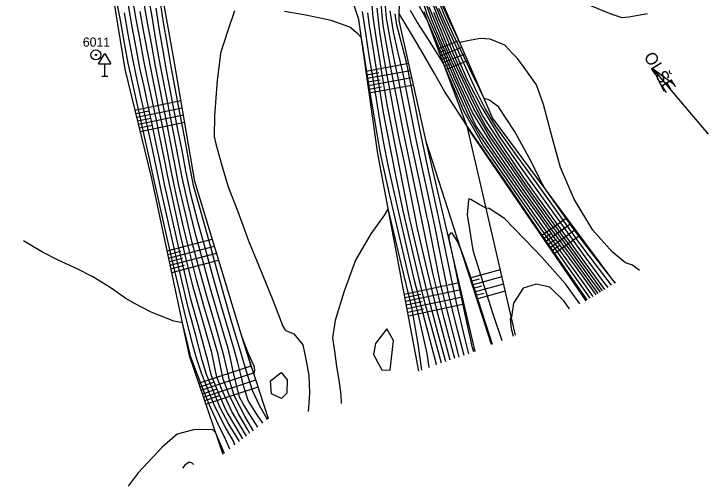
# Model space of a CAD drawing. Extents: x -448957 to -448612, y -1107690 to -1107245.
# Drawn here: x -448752.7 to -448695.5, y -1107690 to -1107651.1 of the extents above; entities that cross this region are included whole.
import ezdxf

# ---------------------------------------------------------------- set-up
doc = ezdxf.new("R2010")
doc.units = 0
for name, color, linetype in [('34', 7, 'Continuous'), ('63', 7, 'Continuous'), ('Default', 7, 'Continuous'), ('Vrstva 1', 7, 'Continuous'), ('Vrstva 14', 7, 'Continuous'), ('Vrstva 15', 7, 'Continuous'), ('Vrstva 16', 7, 'Continuous'), ('Vrstva 17', 7, 'Continuous'), ('Vrstva 2', 7, 'Continuous'), ('Vrstva 34', 7, 'Continuous'), ('Vrstva 45', 7, 'Continuous'), ('Vrstva 63', 7, 'Continuous')]:
    doc.layers.add(name, color=color, linetype=linetype)

# ---------------------------------------------------------------- blocks, each defined once
blk = doc.blocks.new('POINT_DISPLAY')
at = {"layer": 'Default'}
blk.add_line((0, 0), (0, 0), dxfattribs=at)
blk = doc.blocks.new('DZ$0')
at = {"layer": '34'}
for p, q in [((-5, 10), (0, 18.5)), ((0, 18.5), (5, 10)), ((-5, 10), (5, 10)), ((0, 0), (0, 10)), ((-2.49, 0), (2.49, 0))]:
    blk.add_line(p, q, dxfattribs=at)
blk = doc.blocks.new('PPBP$7')
at = {"layer": '63'}
for radius in [4.12, 0.5]:
    blk.add_circle((0, 0), radius, dxfattribs=at)
blk = doc.blocks.new('TOK')
at = {"layer": 'Default'}
for p, q in [((-5, 50), (0, 70)), ((0, 0), (0, 70)), ((0, 70), (5, 50))]:
    blk.add_line(p, q, dxfattribs=at)

msp = doc.modelspace()

# ---------------------------------------------------------------- linework, layer by layer
at = {"layer": 'Vrstva 14'}
for p, q in [((-448724.467, -1107651.591), (-448727.762, -1107641.454)), ((-448721.159, -1107651.66), (-448721.006, -1107642.964)), ((-448743.592, -1107655.643), (-448745.343, -1107644.83)), ((-448739.604, -1107654.794), (-448741.442, -1107644.579)), ((-448713.524, -1107659.615), (-448717.674, -1107650.095)), ((-448715.567, -1107660.428), (-448719.111, -1107650.966)), ((-448722.898, -1107662.583), (-448724.467, -1107651.591)), ((-448718.945, -1107661.555), (-448721.159, -1107651.66)), ((-448737.889, -1107664.827), (-448739.604, -1107654.794)), ((-448741.412, -1107664.597), (-448743.592, -1107655.643)), ((-448703.496, -1107673.142), (-448713.524, -1107659.615)), ((-448705.856, -1107674.58), (-448715.567, -1107660.428)), ((-448711.633, -1107677.388), (-448715.567, -1107660.428)), ((-448714.928, -1107678.724), (-448718.945, -1107661.555)), ((-448713.608, -1107678.158), (-448718.945, -1107661.555)), ((-448719.553, -1107680.342), (-448722.898, -1107662.583)), ((-448738.314, -1107679.081), (-448741.412, -1107664.597)), ((-448733.908, -1107677.93), (-448737.889, -1107664.827)), ((-448731.852, -1107684.228), (-448733.908, -1107677.93)), ((-448735.572, -1107687.149), (-448738.314, -1107679.081))]:
    msp.add_line(p, q, dxfattribs=at)
at = {"layer": 'Vrstva 15'}
for p, q in [((-448717.978, -1107653.99), (-448716.276, -1107653.301)), ((-448717.873, -1107654.271), (-448717.378, -1107654.071)), ((-448717.768, -1107654.552), (-448716.037, -1107653.851)), ((-448717.663, -1107654.833), (-448717.159, -1107654.63)), ((-448717.557, -1107655.114), (-448715.797, -1107654.401)), ((-448723.866, -1107655.804), (-448720.375, -1107655.165)), ((-448717.452, -1107655.395), (-448716.941, -1107655.188)), ((-448717.347, -1107655.676), (-448715.557, -1107654.952)), ((-448723.823, -1107656.101), (-448722.813, -1107655.916)), ((-448723.781, -1107656.398), (-448720.244, -1107655.751)), ((-448723.738, -1107656.696), (-448722.715, -1107656.508)), ((-448723.696, -1107656.993), (-448720.112, -1107656.337)), ((-448723.654, -1107657.29), (-448722.616, -1107657.1)), ((-448723.611, -1107657.587), (-448719.981, -1107656.923)), ((-448742.777, -1107658.989), (-448739.02, -1107658.211)), ((-448742.635, -1107659.572), (-448738.919, -1107658.803)), ((-448742.706, -1107659.281), (-448741.644, -1107659.061)), ((-448742.493, -1107660.155), (-448738.818, -1107659.395)), ((-448742.564, -1107659.864), (-448741.514, -1107659.646)), ((-448742.351, -1107660.739), (-448738.716, -1107659.987)), ((-448742.422, -1107660.447), (-448741.384, -1107660.232)), ((-448709.512, -1107669.252), (-448707.463, -1107667.791)), ((-448709.172, -1107669.747), (-448707.106, -1107668.273)), ((-448709.342, -1107669.5), (-448708.752, -1107669.078)), ((-448708.833, -1107670.242), (-448706.748, -1107668.755)), ((-448740.149, -1107670.5), (-448736.455, -1107669.545)), ((-448709.003, -1107669.994), (-448708.407, -1107669.57)), ((-448708.493, -1107670.737), (-448706.391, -1107669.237)), ((-448740.024, -1107671.087), (-448736.281, -1107670.12)), ((-448708.663, -1107670.489), (-448708.062, -1107670.061)), ((-448740.087, -1107670.793), (-448739.017, -1107670.517)), ((-448739.898, -1107671.674), (-448736.106, -1107670.694)), ((-448739.961, -1107671.38), (-448738.878, -1107671.101)), ((-448739.773, -1107672.261), (-448735.932, -1107671.269)), ((-448739.835, -1107671.968), (-448738.738, -1107671.684)), ((-448715.361, -1107672.706), (-448712.878, -1107672.02)), ((-448720.741, -1107674.034), (-448716.247, -1107673.085)), ((-448715.269, -1107672.992), (-448714.573, -1107672.8)), ((-448715.177, -1107673.278), (-448712.742, -1107672.605)), ((-448720.63, -1107674.624), (-448716.111, -1107673.67)), ((-448715.085, -1107673.563), (-448714.403, -1107673.375)), ((-448714.993, -1107673.849), (-448712.607, -1107673.19)), ((-448720.686, -1107674.329), (-448719.394, -1107674.056)), ((-448720.519, -1107675.213), (-448715.974, -1107674.254)), ((-448714.901, -1107674.135), (-448714.233, -1107673.951)), ((-448714.809, -1107674.421), (-448712.471, -1107673.775)), ((-448720.575, -1107674.918), (-448719.276, -1107674.644)), ((-448720.408, -1107675.803), (-448715.837, -1107674.838)), ((-448720.463, -1107675.508), (-448719.158, -1107675.233)), ((-448737.551, -1107681.326), (-448733.265, -1107679.899)), ((-448737.358, -1107681.894), (-448733.079, -1107680.469)), ((-448737.165, -1107682.463), (-448732.893, -1107681.039)), ((-448737.454, -1107681.61), (-448736.232, -1107681.203)), ((-448736.972, -1107683.031), (-448732.707, -1107681.61)), ((-448737.261, -1107682.179), (-448736.041, -1107681.772)), ((-448737.068, -1107682.747), (-448735.85, -1107682.341))]:
    msp.add_line(p, q, dxfattribs=at)
at = {"layer": 'Vrstva 16'}
for points in [[(-448705.049, -1107674.088), (-448705.094, -1107674.027), (-448706.742, -1107671.759), (-448708.493, -1107669.348), (-448709.575, -1107667.84), (-448711.005, -1107665.85), (-448711.595, -1107665.027), (-448713.199, -1107662.695), (-448714.823, -1107660.339), (-448714.994, -1107660.039), (-448715.689, -1107658.504), (-448716.634, -1107656.378), (-448718.17, -1107652.827), (-448718.828, -1107651.263), (-448719.336, -1107649.7)], [(-448734.596, -1107686.383), (-448734.729, -1107686.068), (-448735.394, -1107684.887), (-448736.238, -1107683.234), (-448736.762, -1107681.942), (-448737.326, -1107680.512), (-448737.745, -1107679.269), (-448738.038, -1107678.173), (-448738.64, -1107675.835), (-448739.163, -1107673.647), (-448739.728, -1107671.23), (-448740.249, -1107668.973), (-448740.791, -1107666.557), (-448741.278, -1107664.37), (-448741.624, -1107662.849), (-448741.978, -1107661.301), (-448742.3, -1107659.8), (-448742.646, -1107658.212), (-448742.99, -1107656.716), (-448743.335, -1107655.149), (-448743.656, -1107653.373), (-448743.963, -1107651.649), (-448744.304, -1107649.85)], [(-448704.067, -1107673.49), (-448704.487, -1107672.947), (-448706.153, -1107670.689), (-448707.934, -1107668.22), (-448709.565, -1107665.94), (-448711.34, -1107663.483), (-448712.956, -1107661.156), (-448714.517, -1107658.573), (-448715.298, -1107657.072), (-448715.555, -1107656.538), (-448716.244, -1107654.957), (-448716.907, -1107653.416), (-448717.597, -1107651.828), (-448718.296, -1107650.163)], [(-448733.099, -1107685.207), (-448733.105, -1107685.197), (-448733.776, -1107684.021), (-448734.661, -1107682.335), (-448735.028, -1107681.178), (-448735.237, -1107680.235), (-448735.479, -1107679.159), (-448736.195, -1107676.593), (-448736.843, -1107674.405), (-448737.502, -1107672.045), (-448738.105, -1107669.824), (-448738.627, -1107667.568), (-448739.179, -1107665.151), (-448739.518, -1107663.426), (-448739.839, -1107661.752), (-448740.145, -1107660.186), (-448740.465, -1107658.559), (-448740.798, -1107656.902), (-448741.102, -1107655.397), (-448741.412, -1107653.697), (-448741.714, -1107651.994), (-448742.018, -1107650.283)], [(-448717.703, -1107679.695), (-448718.244, -1107677.695), (-448719.024, -1107674.813), (-448719.335, -1107673.622), (-448720.832, -1107667.226), (-448721.44, -1107664.331), (-448722.12, -1107660.874), (-448722.438, -1107659.189), (-448722.72, -1107657.481), (-448723.022, -1107655.648), (-448723.298, -1107653.91), (-448723.59, -1107652.078), (-448723.727, -1107651.045)], [(-448715.847, -1107679.045), (-448716.429, -1107676.776), (-448717.144, -1107673.885), (-448717.657, -1107671.34), (-448718.246, -1107668.457), (-448718.821, -1107665.787), (-448719.444, -1107662.914), (-448719.848, -1107660.983), (-448720.175, -1107659.323), (-448720.526, -1107657.559), (-448720.854, -1107655.899), (-448721.235, -1107654.326), (-448721.627, -1107652.594), (-448721.889, -1107650.873)], [(-448707.229, -1107675.247), (-448707.687, -1107674.599), (-448708.837, -1107673.46), (-448709.961, -1107673.235), (-448711.019, -1107673.565), (-448711.811, -1107674.768), (-448711.976, -1107675.909), (-448712.076, -1107676.062), (-448712.006, -1107676.841), (-448711.836, -1107677.467)]]:
    msp.add_lwpolyline(points, dxfattribs=at)
at = {"layer": 'Vrstva 17'}
for points in [[(-448703.454, -1107673.12), (-448703.493, -1107673.078), (-448703.664, -1107672.887), (-448703.796, -1107672.737), (-448705.19, -1107670.934), (-448706.748, -1107668.904), (-448708.093, -1107667.014), (-448709.273, -1107665.349), (-448709.634, -1107664.685), (-448710.393, -1107663.155), (-448711.735, -1107660.719), (-448713.043, -1107658.718), (-448713.81, -1107658.161), (-448714.213, -1107658.034), (-448714.594, -1107657.258), (-448715.069, -1107656.264), (-448715.82, -1107654.713), (-448716.755, -1107652.751), (-448717.475, -1107651.182), (-448718.322, -1107649.043)], [(-448732.713, -1107684.904), (-448733.21, -1107684.149), (-448733.927, -1107683.008), (-448734.217, -1107682.455), (-448734.504, -1107681.354), (-448734.762, -1107680.238), (-448734.975, -1107679.291), (-448735.189, -1107678.382), (-448735.292, -1107678.037), (-448735.942, -1107675.849), (-448736.603, -1107673.601), (-448737.208, -1107671.402), (-448737.866, -1107669.027), (-448738.437, -1107666.658), (-448738.921, -1107664.501), (-448739.238, -1107662.827), (-448739.541, -1107661.244), (-448739.865, -1107659.57), (-448740.169, -1107657.995), (-448740.466, -1107656.482), (-448740.791, -1107654.794), (-448741.086, -1107653.089), (-448741.385, -1107651.345), (-448741.678, -1107649.64)], [(-448704.329, -1107673.649), (-448705.956, -1107671.422), (-448707.61, -1107669.158), (-448708.038, -1107668.568), (-448709.676, -1107666.293), (-448711.034, -1107664.404), (-448712.63, -1107662.042), (-448714.306, -1107659.462), (-448715.07, -1107657.954), (-448715.991, -1107656.035), (-448716.683, -1107654.473), (-448717.291, -1107653.016), (-448717.965, -1107651.418), (-448718.644, -1107649.622)], [(-448701.507, -1107672.098), (-448702.053, -1107671.676), (-448702.651, -1107671.474), (-448703.702, -1107670.605), (-448705.315, -1107668.823), (-448706.853, -1107666.268), (-448707.957, -1107663.7), (-448708.623, -1107661.323), (-448709.345, -1107658.545), (-448709.931, -1107656.94), (-448710.806, -1107655.701), (-448711.467, -1107654.782), (-448711.845, -1107654.386), (-448712.526, -1107653.694), (-448713.704, -1107653.191), (-448714.53, -1107653.144), (-448715.41, -1107653.296), (-448716.203, -1107653.47), (-448716.251, -1107653.372), (-448716.313, -1107653.244), (-448717.048, -1107651.684), (-448717.931, -1107649.679)], [(-448733.661, -1107685.648), (-448734.17, -1107684.793), (-448734.856, -1107683.628), (-448735.549, -1107682.095), (-448736.077, -1107680.825), (-448736.264, -1107679.899), (-448736.487, -1107678.818), (-448736.675, -1107678.146), (-448737.315, -1107675.956), (-448737.975, -1107673.657), (-448738.554, -1107671.298), (-448739.076, -1107669.07), (-448739.612, -1107666.655), (-448740.095, -1107664.427), (-448740.43, -1107662.751), (-448740.74, -1107661.209), (-448741.053, -1107659.693), (-448741.39, -1107658.059), (-448741.715, -1107656.559), (-448742.053, -1107654.951), (-448742.367, -1107653.25), (-448742.678, -1107651.57), (-448742.99, -1107649.788)], [(-448731.936, -1107684.294), (-448732.027, -1107684.155), (-448732.6, -1107683.143), (-448733.15, -1107681.928), (-448733.477, -1107680.874), (-448733.807, -1107679.834), (-448734.115, -1107678.775), (-448734.812, -1107676.455), (-448735.452, -1107674.265), (-448736.111, -1107671.907), (-448736.712, -1107669.707), (-448737.371, -1107667.373), (-448737.985, -1107665.148), (-448738.314, -1107663.434), (-448738.622, -1107661.761), (-448738.927, -1107660.193), (-448739.253, -1107658.518), (-448739.551, -1107656.912), (-448739.855, -1107655.285), (-448740.156, -1107653.532), (-448740.44, -1107651.825), (-448740.723, -1107650.003)], [(-448716.618, -1107679.315), (-448716.724, -1107678.925), (-448717.469, -1107676.031), (-448718.393, -1107672.329), (-448719.015, -1107669.432), (-448719.514, -1107666.916), (-448720.117, -1107664.038), (-448720.834, -1107660.626), (-448721.169, -1107658.968), (-448721.521, -1107657.212), (-448721.851, -1107655.532), (-448722.143, -1107653.892), (-448722.464, -1107652.059), (-448722.557, -1107651.204), (-448722.635, -1107650.216)], [(-448704.869, -1107673.979), (-448705.309, -1107673.376), (-448706.959, -1107671.109), (-448708.712, -1107668.694), (-448710.377, -1107666.379), (-448711.88, -1107664.245), (-448713.496, -1107661.885), (-448715.152, -1107659.205), (-448715.867, -1107657.677), (-448716.266, -1107656.784), (-448716.942, -1107655.241), (-448717.83, -1107653.204), (-448718.485, -1107651.623), (-448719.038, -1107650.065)], [(-448733.941, -1107685.869), (-448734.518, -1107684.901), (-448735.211, -1107683.743), (-448735.367, -1107683.455), (-448735.903, -1107682.173), (-448736.505, -1107680.712), (-448736.789, -1107679.584), (-448737.573, -1107676.647), (-448738.208, -1107674.445), (-448738.73, -1107672.222), (-448739.297, -1107669.805), (-448739.815, -1107667.469), (-448740.349, -1107665.054), (-448740.695, -1107663.383), (-448741.035, -1107661.75), (-448741.377, -1107660.142), (-448741.691, -1107658.639), (-448742.038, -1107657.059), (-448742.37, -1107655.56), (-448742.688, -1107653.905), (-448743.006, -1107652.193), (-448743.31, -1107650.453)], [(-448732.324, -1107684.599), (-448732.84, -1107683.814), (-448733.522, -1107682.729), (-448733.834, -1107681.705), (-448734.104, -1107680.636), (-448734.373, -1107679.645), (-448734.652, -1107678.579), (-448735.052, -1107677.246), (-448735.697, -1107675.057), (-448736.357, -1107672.754), (-448736.96, -1107670.554), (-448737.618, -1107668.2), (-448738.211, -1107665.903), (-448738.618, -1107663.968), (-448738.93, -1107662.294), (-448739.234, -1107660.719), (-448739.559, -1107659.044), (-448739.86, -1107657.454), (-448740.16, -1107655.883), (-448740.473, -1107654.163), (-448740.763, -1107652.457), (-448741.054, -1107650.674)], [(-448717.342, -1107679.568), (-448717.961, -1107677.279), (-448718.732, -1107674.394), (-448719.514, -1107671.143), (-448720.203, -1107668.229), (-448720.275, -1107667.921), (-448720.356, -1107667.524), (-448720.851, -1107665.017), (-448721.346, -1107662.528), (-448721.461, -1107661.982), (-448721.785, -1107660.321), (-448722.133, -1107658.539), (-448722.44, -1107656.742), (-448722.723, -1107655.043), (-448723.015, -1107653.21), (-448723.277, -1107651.411), (-448723.369, -1107650.422)], [(-448716.98, -1107679.442), (-448717.342, -1107678.102), (-448718.101, -1107675.213), (-448718.99, -1107671.58), (-448719.647, -1107668.675), (-448720.143, -1107666.165), (-448720.732, -1107663.283), (-448721.148, -1107661.304), (-448721.477, -1107659.645), (-448721.827, -1107657.876), (-448722.146, -1107656.137), (-448722.433, -1107654.468), (-448722.739, -1107652.635), (-448722.957, -1107650.665)], [(-448716.239, -1107679.183), (-448716.702, -1107677.374), (-448717.444, -1107674.478), (-448717.796, -1107673.079), (-448718.297, -1107670.622), (-448718.797, -1107668.102), (-448718.884, -1107667.67), (-448719.453, -1107665.012), (-448720.07, -1107662.137), (-448720.165, -1107661.682), (-448720.499, -1107660.024), (-448720.852, -1107658.274), (-448721.183, -1107656.615), (-448721.546, -1107654.929), (-448721.897, -1107653.134), (-448722.183, -1107651.476), (-448722.278, -1107650.487)], [(-448705.525, -1107674.378), (-448706.275, -1107673.339), (-448707.908, -1107671.022), (-448709.414, -1107668.884), (-448711.056, -1107666.535), (-448712.671, -1107664.183), (-448714.308, -1107661.832), (-448715.878, -1107659.074), (-448716.534, -1107657.523), (-448717.095, -1107656.216), (-448717.528, -1107655.193), (-448717.839, -1107654.694), (-448718.773, -1107653.227), (-448719.701, -1107651.764), (-448720.232, -1107650.845)], [(-448705.284, -1107674.231), (-448706.58, -1107672.434), (-448708.218, -1107670.143), (-448709.663, -1107668.122), (-448711.325, -1107665.781), (-448712.935, -1107663.439), (-448714.566, -1107661.085), (-448715.436, -1107659.557), (-448716.111, -1107658.013), (-448717.002, -1107655.971), (-448717.663, -1107654.422), (-448718.351, -1107652.823), (-448718.885, -1107651.57), (-448719.064, -1107651.291), (-448719.509, -1107650.522)], [(-448704.689, -1107673.869), (-448705.525, -1107672.725), (-448707.176, -1107670.458), (-448708.931, -1107668.04), (-448710.589, -1107665.741), (-448712.17, -1107663.456), (-448713.777, -1107661.093), (-448715.078, -1107658.842), (-448715.81, -1107657.322), (-448716.259, -1107656.365), (-448716.945, -1107654.826), (-448717.49, -1107653.581), (-448718.142, -1107651.982), (-448718.696, -1107650.579)], [(-448703.777, -1107673.313), (-448704.761, -1107672.04), (-448706.451, -1107669.796), (-448708.266, -1107667.26), (-448709.891, -1107664.978), (-448711.645, -1107662.562), (-448713.282, -1107660.27), (-448714.111, -1107658.858), (-448714.886, -1107657.338), (-448715.685, -1107655.585), (-448716.398, -1107654.011), (-448717.196, -1107652.259), (-448717.902, -1107650.681)], [(-448700.829, -1107651.137), (-448702.369, -1107651.4), (-448702.907, -1107651.463), (-448703.82, -1107651.145), (-448705.475, -1107650.46)], [(-448734.222, -1107686.089), (-448734.384, -1107685.818), (-448735.087, -1107684.666), (-448735.803, -1107683.345), (-448736.333, -1107682.057), (-448736.916, -1107680.612), (-448737.267, -1107679.426), (-448737.806, -1107677.41), (-448738.424, -1107675.14), (-448738.946, -1107672.935), (-448739.512, -1107670.518), (-448740.032, -1107668.221), (-448740.57, -1107665.806), (-448740.987, -1107663.876), (-448741.33, -1107662.299), (-448741.677, -1107660.722), (-448741.996, -1107659.22), (-448742.342, -1107657.636), (-448742.68, -1107656.138), (-448743.011, -1107654.527), (-448743.331, -1107652.783), (-448743.637, -1107651.051)], [(-448733.38, -1107685.428), (-448733.637, -1107684.995), (-448734.316, -1107683.824), (-448735.105, -1107682.215), (-448735.553, -1107681.001), (-448735.751, -1107680.067), (-448735.983, -1107678.988), (-448736.435, -1107677.37), (-448737.079, -1107675.181), (-448737.738, -1107672.851), (-448738.33, -1107670.561), (-448738.851, -1107668.319), (-448739.396, -1107665.903), (-448739.807, -1107663.926), (-448740.135, -1107662.252), (-448740.442, -1107660.697), (-448740.759, -1107659.126), (-448741.094, -1107657.481), (-448741.409, -1107655.978), (-448741.733, -1107654.324), (-448742.04, -1107652.622), (-448742.348, -1107650.927)], [(-448734.638, -1107650.887), (-448735.216, -1107652.561), (-448735.772, -1107654.337), (-448735.842, -1107654.844), (-448736.048, -1107656.548), (-448736.269, -1107659.468), (-448736.302, -1107661.153), (-448736.166, -1107661.748), (-448735.733, -1107663.325), (-448735.139, -1107665.261), (-448734.372, -1107667.284), (-448733.484, -1107669.675), (-448732.654, -1107671.728), (-448731.499, -1107674.526), (-448730.672, -1107676.659), (-448730.521, -1107676.939), (-448730.428, -1107677.004), (-448729.781, -1107677.29), (-448729.052, -1107678.18), (-448728.776, -1107679.506), (-448728.55, -1107680.687), (-448728.5, -1107682.115), (-448728.568, -1107683.349), (-448728.602, -1107683.638)], [(-448718.708, -1107680.046), (-448718.868, -1107678.895), (-448719.51, -1107675.965), (-448720.449, -1107672.232), (-448721.946, -1107665.836), (-448722.613, -1107662.924), (-448722.746, -1107662.249), (-448723.05, -1107660.445), (-448723.63, -1107656.9), (-448723.911, -1107655.185), (-448724.088, -1107654.098), (-448724.254, -1107653.082), (-448724.525, -1107652.781), (-448725.203, -1107652.211), (-448726.718, -1107651.662), (-448728.803, -1107651.246), (-448730.535, -1107650.934)], [(-448718.102, -1107679.834), (-448718.122, -1107679.685), (-448718.885, -1107676.797), (-448719.892, -1107672.927), (-448721.389, -1107666.531), (-448722.027, -1107663.628), (-448722.433, -1107661.562), (-448722.744, -1107659.817), (-448723.025, -1107658.107), (-448723.326, -1107656.274), (-448723.604, -1107654.548), (-448723.9, -1107652.715), (-448724.154, -1107650.933)], [(-448715.455, -1107678.908), (-448715.789, -1107677.606), (-448716.462, -1107674.722), (-448717.002, -1107672.123), (-448717.608, -1107669.245), (-448718.189, -1107666.563), (-448718.819, -1107663.691), (-448719.531, -1107660.284), (-448719.852, -1107658.622), (-448720.2, -1107656.844), (-448720.524, -1107655.183), (-448720.924, -1107653.724), (-448721.356, -1107652.054), (-448721.491, -1107651.13)], [(-448705.767, -1107674.526), (-448705.969, -1107674.245), (-448707.599, -1107671.9), (-448709.164, -1107669.646), (-448710.787, -1107667.289), (-448712.408, -1107664.927), (-448714.051, -1107662.578), (-448715.603, -1107660.322), (-448715.645, -1107660.219), (-448716.536, -1107658.861), (-448717.433, -1107657.495), (-448718.274, -1107656.003), (-448719.382, -1107654.07), (-448720.266, -1107652.593), (-448721.013, -1107651.333), (-448721.149, -1107651.101)], [(-448704.509, -1107673.759), (-448705.74, -1107672.074), (-448707.393, -1107669.808), (-448709.151, -1107667.386), (-448710.802, -1107665.103), (-448712.46, -1107662.667), (-448714.058, -1107660.3), (-448714.505, -1107659.528), (-448715.252, -1107658.013), (-448716.427, -1107655.531), (-448717.121, -1107653.99), (-448717.675, -1107652.616), (-448718.333, -1107651.008)], [(-448706.386, -1107674.838), (-448707.542, -1107673.203), (-448709.491, -1107671.005), (-448710.904, -1107669.535), (-448712.546, -1107667.854), (-448713.804, -1107667.052), (-448714.037, -1107667.024), (-448714.603, -1107666.705), (-448715.299, -1107666.316), (-448715.458, -1107666.239), (-448715.491, -1107666.364), (-448715.597, -1107667.54), (-448715.124, -1107670.441), (-448714.378, -1107672.897), (-448713.484, -1107675.663), (-448712.761, -1107677.828)], [(-448719.314, -1107680.258), (-448719.613, -1107678.105), (-448720.135, -1107675.133), (-448721.006, -1107671.537), (-448722.059, -1107667.035), (-448722.371, -1107667.571), (-448723.477, -1107669.114), (-448724.742, -1107671.272), (-448725.665, -1107673.79), (-448726.396, -1107676.183), (-448726.607, -1107677.621), (-448726.438, -1107678.705), (-448726.29, -1107679.946), (-448726.108, -1107681.035), (-448725.945, -1107682.269), (-448725.919, -1107682.983)], [(-448715.063, -1107678.771), (-448715.149, -1107678.437), (-448715.78, -1107675.56), (-448716.346, -1107672.906), (-448716.725, -1107671.156), (-448717.082, -1107669.517), (-448717.078, -1107669.225), (-448716.889, -1107668.998), (-448716.392, -1107669.765), (-448716.081, -1107670.465), (-448715.711, -1107671.536), (-448715.269, -1107672.82), (-448714.377, -1107675.587), (-448713.558, -1107678.138)], [(-448735.029, -1107686.722), (-448735.379, -1107685.892), (-448735.978, -1107684.659), (-448736.674, -1107683.124), (-448737.191, -1107681.826), (-448737.737, -1107680.411), (-448738.223, -1107679.111), (-448738.27, -1107678.936), (-448738.599, -1107677.596), (-448738.892, -1107676.38), (-448739.59, -1107676.245), (-448741.44, -1107675.522), (-448742.821, -1107674.814), (-448743.514, -1107674.39), (-448744.807, -1107673.51), (-448746.219, -1107672.631), (-448747.514, -1107671.979), (-448749.051, -1107671.27), (-448750.347, -1107670.619), (-448751.362, -1107669.999), (-448751.906, -1107669.671)], [(-448721.636, -1107677.822), (-448722.175, -1107676.876), (-448723.1, -1107678.072), (-448723.266, -1107678.975), (-448722.589, -1107680.221), (-448721.885, -1107680.264), (-448721.636, -1107677.822)], [(-448733.946, -1107677.746), (-448733.516, -1107678.892), (-448733.057, -1107679.906), (-448733.004, -1107680.252), (-448733.05, -1107680.557), (-448733.145, -1107680.295), (-448733.242, -1107680.023), (-448733.578, -1107678.972), (-448733.964, -1107677.752), (-448734.017, -1107677.573), (-448733.946, -1107677.746)], [(-448731.614, -1107682.182), (-448731.676, -1107681.135), (-448730.819, -1107680.442), (-448730.316, -1107681.05), (-448730.34, -1107682.124), (-448730.781, -1107682.562), (-448731.614, -1107682.182)], [(-448735.462, -1107687.062), (-448736.178, -1107685.365), (-448736.43, -1107685.1), (-448737.982, -1107685.141), (-448739.33, -1107685.5), (-448740.541, -1107686.542), (-448742.517, -1107688.638), (-448743.329, -1107689.745)], [(-448737.986, -1107687.957), (-448738.092, -1107687.846), (-448738.34, -1107687.768), (-448738.685, -1107688.03), (-448738.889, -1107688.259)]]:
    msp.add_lwpolyline(points, dxfattribs=at)

# ---------------------------------------------------------------- block references
at = {"layer": 'Vrstva 1', "xscale": 0.1, "yscale": 0.10000000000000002}
for p in [(-448724.467, -1107651.591), (-448721.159, -1107651.66), (-448721.159, -1107651.66), (-448739.604, -1107654.794), (-448743.592, -1107655.643), (-448713.524, -1107659.615), (-448715.567, -1107660.428), (-448715.567, -1107660.428), (-448718.945, -1107661.555), (-448718.945, -1107661.555), (-448722.898, -1107662.583), (-448741.412, -1107664.597), (-448737.889, -1107664.827), (-448703.496, -1107673.142), (-448705.856, -1107674.58), (-448711.633, -1107677.388), (-448733.908, -1107677.93), (-448713.608, -1107678.158), (-448714.928, -1107678.724), (-448738.314, -1107679.081), (-448719.553, -1107680.342), (-448731.852, -1107684.228), (-448735.572, -1107687.149)]:
    msp.add_blockref('POINT_DISPLAY', p, dxfattribs=at)
at = {"layer": 'Vrstva 14', "xscale": 0.1, "yscale": 0.10000000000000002}
for p in [(-448733.652, -1107654.409), (-448703.278, -1107654.955), (-448751.098, -1107656.961), (-448708.852, -1107657.038), (-448728.897, -1107663.567), (-448752.679, -1107667.581), (-448699.601, -1107671.097), (-448728.693, -1107676.321), (-448748.564, -1107678.71), (-448726.637, -1107683.281), (-448744.006, -1107689.972)]:
    msp.add_blockref('POINT_DISPLAY', p, dxfattribs=at)
at = {"layer": 'Vrstva 34', "xscale": 0.1, "yscale": 0.10000000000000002}
msp.add_blockref('DZ$0', (-448745.25, -1107656.21), dxfattribs=at)
at = {"layer": 'Vrstva 45', "xscale": 0.10000000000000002, "yscale": 0.1, "rotation": 40.21810754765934}
msp.add_blockref('TOK', (-448695.86, -1107660.976), dxfattribs=at)
at = {"layer": 'Vrstva 63', "xscale": 0.1, "yscale": 0.10000000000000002}
msp.add_blockref('PPBP$7', (-448745.974, -1107654.485), dxfattribs=at)

# ---------------------------------------------------------------- texts
at = {"layer": 'Vrstva 2'}
msp.add_text('6011', height=0.75, dxfattribs=at).set_placement((-448747.045, -1107653.81))
at = {"layer": 'Vrstva 45'}
msp.add_text('OLŠE', height=1, rotation=301.6241, dxfattribs=at).set_placement((-448701.183, -1107654.618))

doc.saveas('drawing.dxf')
